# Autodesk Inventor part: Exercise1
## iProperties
Shininess: 77.0
Length Units: 11269
Angle Units: 11279
Time Units: 11290
Mass Units: 11283
Length Display Precision: 3
Angle Display Precision: 2
Created: 2001-11
Part Number: Exercise1
Document SubType Name: Modeling
Designer: Renu Muthoo
Density: 0.0
Volumn: 0.0
Area: 0.0
PropertySet Name: Model Information
Control State: 0
Master: False
Checked Out: False
Author: Renu Muthoo
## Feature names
1. Extrusion1
2. Extrusion2
3. Extrusion3
4. Extrusion4
